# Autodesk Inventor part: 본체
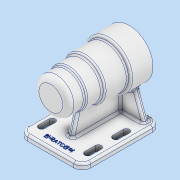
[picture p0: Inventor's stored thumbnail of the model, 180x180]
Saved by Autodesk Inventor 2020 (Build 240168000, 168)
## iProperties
Created: 2021-10
Part Number: 본체
Material: 알루미늄 6061
Document SubType Name: Modeling
Designer: user
Density: 2.7 g/cm^3
Appearance: 알루미늄 - 평지
Mass: 692.089 g
Surface Area: 699.205 cm^2
Volume: 256.329 cm^3
Author: user
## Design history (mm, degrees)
sketch "스케치1"
  geometry: L1 (-45, -56)-(45, -56); L2 (45, -56)-(45, 56); L3 (45, 56)-(-45, 56); L4 (-45, 56)-(-45, -56); L5 (-45, -56)-(45, 56); L6 (45, -56)-(-45, 56); 1 further point
  constraints: 12 end point, 2 midpoint, 2 parallel, 1 horizontal, 1 perpendicular
  dimensions: "d0" = 112 distance of L1.end L2.end; "d1" = 90 distance of L2.end L3.end
extrude "돌출1" new body sketch "스케치1" distance "d2" = 8; taper "d3" = 0 deg
sketch "스케치2"
  geometry: L1 (70, 50)-(80.5, 50); L2 (80.5, 50)-(80.5, 47); L3 (80.5, 47)-(86, 47); L4 (86, 47)-(86, 43); L5 (86, 43)-(87.5, 43); L6 (87.5, 43)-(87.5, 25); L7 (87.5, 25)-(91, 25); L8 (91, 25)-(91, 13); L9 (91, 13)-(94, 13); L10 (94, 13)-(94, -41); L11 (94, -41)-(91, -41); L12 (91, -41)-(91, -56); L13 (70, 50)-(70, 56); L14 (70, 56)-(95, 56); L15 (95, 56)-(95, 32); L16 (95, 32)-(97, 32); L17 (97, 32)-(97, 10); L18 (97, 10)-(100, 10); L19 (100, 10)-(100, -24); L20 (100, -24)-(104, -24); L21 (104, -24)-(104, -56); L22 (104, -56)-(91, -56); L23 (0, 56)-(0, -56) reference; L24 (0, -56)-(8, -56) reference; 1 further point
  constraints: 44 end point, 20 perpendicular, 1 horizontal, 1 vertical
  dimensions: "d4" = 112 distance between parallel lines of L22 L14; "d5" = 24 distance of L14.end L15.end; "d6" = 46 distance between parallel lines of L18 L14; "d7" = 80 distance between parallel lines of L20 L14; "d9" = 70 distance between parallel lines of L23 L13; "d10" = 50 diameter of L15 L13; "d11" = 54 diameter of L17 L13; "d12" = 60 diameter of L19 L13; "d13" = 68 diameter of L21 L13; "d14" = 21 diameter of L2 L13; "d15" = 32 diameter of L4 L13; "d16" = 35 diameter of L6 L13; "d17" = 42 diameter of L8 L13; "d18" = 48 diameter of L10 L13; "d19" = 42 diameter of L12 L13; "d20" = 18 distance between parallel lines of L7 L5; "d21" = 12 distance between parallel lines of L9 L7; "d22" = 54 distance between parallel lines of L11 L9; "d23" = 15 distance between parallel lines of L22 L11; "d24" = 0 distance between parallel lines of L24 L22; "d25" = 4 distance between parallel lines of L3 L5; "d26" = 3 distance between parallel lines of L1 L3
revolve "회전1" sketch "스케치2" stored, may be unused: angle "d27" = 90 deg
sketch "스케치3"
  geometry: L1 (-4, -29)-(4, -29); L2 (4, -29)-(4, 48); L3 (4, 48)-(-4, 48); L4 (-4, 48)-(-4, -29); L5 (45, 56)-(-45, 56) reference; 1 further point
  constraints: 8 end point, 2 parallel, 1 horizontal, 1 perpendicular
  dimensions: "d28" = 8 distance between parallel lines of L2 L4; "d29" = 8 distance between parallel lines of L5 L3; "d30" = 4 distance from line of L4 point (0, 0); "d31" = 77 distance between parallel lines of L1 L3
extrude "돌출2" join sketch "스케치3" stored distance "d32" = 8; taper "d33" = 0 deg
sketch "스케치4"
  geometry: L1 (-19.409, 37.342)-(-33, 0); L2 (49, 0)-(-41, 0) reference; L3 (-41, -8)-(-41, 0) reference; L4 (-41, -8)-(-41, 0) reference; L5 (-41, 0)-(0, 0) reference; L6 (0, 0)-(0, 28.236) reference; L7 (8, 28.236)-(8, 0) reference; L8 (8, 0)-(49, 0) reference; L9 (49, 0)-(49, -8) reference; L10 (49, -8)-(-41, -8) reference; L11 (0, 0)-(8, 0) reference; C1 r 21 at (4, 62) reference; A1 r 34 centre (4, 62) between (8, 28.236) and (0, 28.236) reference; A2 r 34 centre (4, 62) between (8, 28.236) and (0, 28.236) reference; A3 r 34 centre (4, 62) between (0, 28.236) and (8, 28.236) reference; 1 further point
  constraints: 2 end point, 1 point on circle, 1 point on line
  dimensions: "d34" = 110 deg angle of L2 L1; "d35" = 8 distance from line of L3 L1.end
extrude "돌출3" join sketch "스케치4" distance "d36" = 8; taper "d37" = 0 deg
sketch "스케치5"
  geometry: L1 (33, -36)-(33, -21); L2 (37.5, -36)-(37.5, -21); L3 (28.5, -21)-(28.5, -36); L4 (-45, -56)-(45, -56) reference; L5 (45, -56)-(45, 56) reference; L6 (-45, -56)-(45, -56) reference; L7 (-45, 56)-(-45, -56) reference; L8 (45, 56)-(-45, 56) reference; L9 (33, 4)-(33, 19); L10 (37.5, 4)-(37.5, 19); L11 (28.5, 19)-(28.5, 4); A1 r 4.5 centre (33, -36) between (28.5, -36) and (37.5, -36); A2 r 4.5 centre (33, -21) between (37.5, -21) and (28.5, -21); A3 r 4.5 centre (33, 4) between (28.5, 4) and (37.5, 4); A4 r 4.5 centre (33, 19) between (37.5, 19) and (28.5, 19); 3 further points
  constraints: 16 end point, 8 point on circle, 8 tangent, 4 centre point, 2 midpoint, 2 parallel, 2 point on line, 1 vertical
  dimensions: "d38" = 15 distance of L1.end L1.start; "d39" = 9 distance between parallel lines of L2 L3; "d40" = 20 distance from line of L1.start L4; "d41" = 33 horizontal distance of point (33, -28.5) point (0, 0); "d42" = 9 distance between parallel lines of L10 L11; "d43" = 15 distance of L9.end L9.start; "d44" = 25 distance of L9.start L1.end
extrude "돌출4" cut sketch "스케치5" distance "d45" = 10; taper "d46" = 0 deg
fillet "모깎기1" dims "d47" = 8
feature "면 기울기1" dims angle "d48" = 15 deg
sketch "스케치6" dims "d49" = 52
  geometry: L1 (13, 22.517)-(0, 0); L2 (0, 0)-(-47.6, 0); C1 r 10.5 at (0, 0) reference; A1 r 27 centre (0, 0) between (4, -26.702) and (-4, -26.702) reference; 2 further points
  constraints: 4 end point, 1 horizontal, 4 other
  dimensions: "d50" = 120 deg angle of L2 L1
hole "구멍1" sketch "스케치6" at (13, 22.517) diameter "d51" = 3.242; stored, may be unused: countersink angle "d55" = 90 deg, drill point angle "d57" = 118 deg; dims "d52" = 8, "d53" = 4, "d54" = 2, "d56" = 11
fillet "모깎기2" dims "d61" = 12
fillet "모깎기3" dims "d62" = 3
sketch "스케치7"
  geometry: L1 (-33, -56)-(33, -56) reference; 2 further points
  constraints: 1 other
  dimensions: "d63" = 12 distance from line of L1 point (0, -44); "d64" = 0 horizontal distance of point (0, 0) point (0, -44)
feature "엠보싱1" sketch "스케치7" dims "d0" = 112, "d1" = 90, "d4" = 112, "d5" = 24, "d6" = 46, "d7" = 80, "d9" = 70, "d10" = 50, "d11" = 54, "d12" = 60, "d13" = 68, "d14" = 21, "d15" = 32, "d16" = 35, "d17" = 42, "d18" = 48, "d19" = 42, "d20" = 18, "d21" = 12, "d22" = 54, "d23" = 15, "d24" = 0, "d25" = 4, "d26" = 3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
fillet "모깎기4" dims "d67" = 3
fillet "모깎기5" dims "d68" = 3
fillet "모깎기6" dims "d69" = 3
fillet "모깎기7" dims "d70" = 3
fillet "모깎기8" dims "d71" = 3
fillet "모깎기9" dims "d72" = 3
fillet "모깎기10" dims "d73" = 3
fillet "모깎기11" dims "d74" = 0.3
fillet "모깎기12" dims "d75" = 3
chamfer "모따기1" distance "d76" = 1; stored, may be unused: second distance "d77" = 2, angle "d78" = 45 deg
node "솔리드1"
mirror "미러1"
mirror "미러2"
pattern_circular "원형 패턴1" dims angle "d59" = 360 deg
node "투영된 루프1"
node "절단 모서리 투영1"
feature "A9D066F2-1C7D-4E18-AEED-F7BC21143FA4" dims "d51" = 3.242, "d52" = 8, "d53" = 4, "d54" = 2, "d55" = 90 deg, "d56" = 11, "d57" = 118 deg
